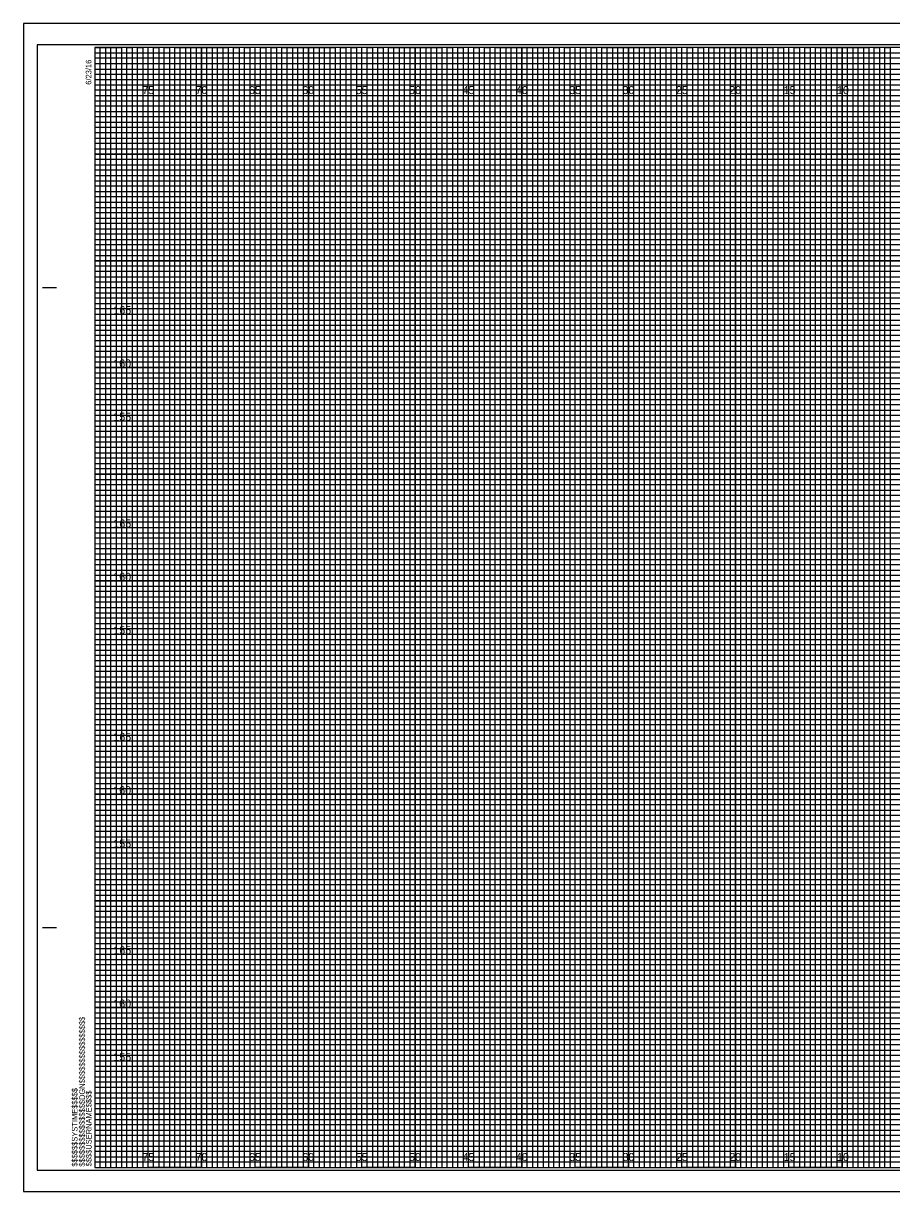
# Model space of a CAD drawing. Extents: x -7 to 162, y 328 to 437.
# Drawn here: x -6.7 to 74.6, y 327.7 to 437.2 of the extents above; entities that cross this region are included whole.
import ezdxf

# ---------------------------------------------------------------- set-up
doc = ezdxf.new("R2010")
doc.units = 0
for name, color, linetype in [('Exist Cross Section Cell', 7, 'Continuous'), ('Exist XS Center Line Elevation Label', 7, 'Continuous'), ('Exist XS Ground Line', 7, 'Continuous'), ('Prop CMT Conc Surface', 7, 'Continuous'), ('Prop CMT Concrete Structures', 7, 'Continuous'), ('Prop CMT Pvmt Course 1', 7, 'Continuous'), ('Prop CMT Pvmt Course 2', 7, 'Continuous'), ('Prop CMT Pvmt Course 3', 7, 'Continuous'), ('Prop CMT Slope Grass', 7, 'Continuous'), ('Prop CMT Subgrade Earthwork', 7, 'Continuous'), ('Scratch_Level_0', 7, 'Continuous')]:
    doc.layers.add(name, color=color, linetype=linetype)

msp = doc.modelspace()

# ---------------------------------------------------------------- linework, layer by layer
at = {"layer": 'Exist XS Center Line Elevation Label'}
for points in [[(0, 435), (2.5, 435), (2.5, 330), (7.5, 330), (7.5, 435), (12.5, 435), (12.5, 330), (17.5, 330), (17.5, 435), (22.5, 435), (22.5, 330), (27.5, 330), (27.5, 435), (32.5, 435), (32.5, 330), (37.5, 330), (37.5, 435), (42.5, 435), (42.5, 330), (47.5, 330), (47.5, 435), (52.5, 435), (52.5, 330), (57.5, 330), (57.5, 435), (62.5, 435), (62.5, 330), (67.5, 330), (67.5, 435), (72.5, 435), (72.5, 330), (77.5, 330)], [(0, 432.5), (137.5, 432.5)], [(0, 422.5), (160, 422.5), (160, 427.5), (0, 427.5)], [(0, 412.5), (160, 412.5), (160, 417.5), (0, 417.5)], [(0, 402.5), (160, 402.5), (160, 407.5), (0, 407.5)], [(0, 392.5), (160, 392.5), (160, 397.5), (0, 397.5)], [(0, 382.5), (160, 382.5), (160, 387.5), (0, 387.5)], [(0, 372.5), (160, 372.5), (160, 377.5), (0, 377.5)], [(0, 362.5), (160, 362.5), (160, 367.5), (0, 367.5)], [(0, 352.5), (160, 352.5), (160, 357.5), (0, 357.5)], [(0, 342.5), (160, 342.5), (160, 347.5), (0, 347.5)], [(0, 332.5), (160, 332.5), (160, 337.5), (0, 337.5)]]:
    msp.add_lwpolyline(points, dxfattribs=at)
at = {"layer": 'Exist XS Ground Line'}
for p, q in [((5, 435), (0, 435)), ((5, 330), (5, 435)), ((15, 435), (10, 435)), ((10, 435), (10, 330)), ((15, 330), (15, 435)), ((25, 435), (20, 435)), ((20, 435), (20, 330)), ((25, 330), (25, 435)), ((35, 435), (30, 435)), ((30, 435), (30, 330)), ((35, 330), (35, 435)), ((45, 435), (40, 435)), ((40, 435), (40, 330)), ((45, 330), (45, 435)), ((55, 435), (50, 435)), ((50, 435), (50, 330)), ((55, 330), (55, 435)), ((65, 435), (60, 435)), ((60, 435), (60, 330)), ((65, 330), (65, 435)), ((75, 435), (70, 435)), ((70, 435), (70, 330)), ((10, 330), (5, 330)), ((20, 330), (15, 330)), ((30, 330), (25, 330)), ((40, 330), (35, 330)), ((50, 330), (45, 330)), ((60, 330), (55, 330)), ((70, 330), (65, 330))]:
    msp.add_line(p, q, dxfattribs=at)
for points in [[(0, 430), (160, 430), (160, 425), (0, 425)], [(0, 420), (160, 420), (160, 415), (0, 415)], [(0, 410), (160, 410), (160, 405), (0, 405)], [(0, 400), (160, 400), (160, 395), (0, 395)], [(0, 390), (160, 390), (160, 385), (0, 385)], [(0, 380), (160, 380), (160, 375), (0, 375)], [(0, 370), (160, 370), (160, 365), (0, 365)], [(0, 360), (160, 360), (160, 355), (0, 355)], [(0, 350), (160, 350), (160, 345), (0, 345)], [(0, 340), (160, 340), (160, 335), (0, 335)]]:
    msp.add_lwpolyline(points, dxfattribs=at)
at = {"layer": 'Prop CMT Conc Surface'}
for p, q in [((5, 330), (5, 435)), ((10, 330), (10, 435)), ((15, 330), (15, 435)), ((20, 330), (20, 435)), ((25, 330), (25, 435)), ((30, 330), (30, 435)), ((35, 330), (35, 435)), ((40, 330), (40, 435)), ((45, 330), (45, 435)), ((50, 330), (50, 435)), ((55, 330), (55, 435)), ((60, 330), (60, 435)), ((65, 330), (65, 435)), ((70, 330), (70, 435)), ((0, 430), (160, 430)), ((0, 425), (160, 425)), ((0, 420), (160, 420)), ((0, 415), (160, 415)), ((0, 410), (160, 410)), ((0, 405), (160, 405)), ((0, 400), (160, 400)), ((0, 395), (160, 395)), ((0, 390), (160, 390)), ((0, 385), (160, 385)), ((0, 380), (160, 380)), ((0, 375), (160, 375)), ((0, 370), (160, 370)), ((0, 365), (160, 365)), ((0, 360), (160, 360)), ((0, 355), (160, 355)), ((0, 350), (160, 350)), ((0, 345), (160, 345)), ((0, 340), (160, 340)), ((0, 335), (160, 335))]:
    msp.add_line(p, q, dxfattribs=at)
at = {"layer": 'Prop CMT Pvmt Course 1'}
for points in [[(0, 330), (0.5, 330), (0.5, 435), (1, 435), (1, 330)], [(1, 330), (1.5, 330), (1.5, 435), (2, 435), (2, 330)], [(2.5, 330), (3, 330), (3, 435), (3.5, 435), (3.5, 330)], [(3.5, 330), (4, 330), (4, 435), (4.5, 435), (4.5, 330)], [(5, 330), (5.5, 330), (5.5, 435), (6, 435), (6, 330)], [(6, 330), (6.5, 330), (6.5, 435), (7, 435), (7, 330)], [(7.5, 330), (8, 330), (8, 435), (8.5, 435), (8.5, 330)], [(8.5, 330), (9, 330), (9, 435), (9.5, 435), (9.5, 330)], [(10, 330), (10.5, 330), (10.5, 435), (11, 435), (11, 330)], [(11, 330), (11.5, 330), (11.5, 435), (12, 435), (12, 330)], [(12.5, 330), (13, 330), (13, 435), (13.5, 435), (13.5, 330)], [(13.5, 330), (14, 330), (14, 435), (14.5, 435), (14.5, 330)], [(15, 330), (15.5, 330), (15.5, 435), (16, 435), (16, 330)], [(16, 330), (16.5, 330), (16.5, 435), (17, 435), (17, 330)], [(17.5, 330), (18, 330), (18, 435), (18.5, 435), (18.5, 330)], [(18.5, 330), (19, 330), (19, 435), (19.5, 435), (19.5, 330)], [(20, 330), (20.5, 330), (20.5, 435), (21, 435), (21, 330)], [(21, 330), (21.5, 330), (21.5, 435), (22, 435), (22, 330)], [(22.5, 330), (23, 330), (23, 435), (23.5, 435), (23.5, 330)], [(23.5, 330), (24, 330), (24, 435), (24.5, 435), (24.5, 330)], [(25, 330), (25.5, 330), (25.5, 435), (26, 435), (26, 330)], [(26, 330), (26.5, 330), (26.5, 435), (27, 435), (27, 330)], [(27.5, 330), (28, 330), (28, 435), (28.5, 435), (28.5, 330)], [(28.5, 330), (29, 330), (29, 435), (29.5, 435), (29.5, 330)], [(30, 330), (30.5, 330), (30.5, 435), (31, 435), (31, 330)], [(31, 330), (31.5, 330), (31.5, 435), (32, 435), (32, 330)], [(32.5, 330), (33, 330), (33, 435), (33.5, 435), (33.5, 330)], [(33.5, 330), (34, 330), (34, 435), (34.5, 435), (34.5, 330)], [(35, 330), (35.5, 330), (35.5, 435), (36, 435), (36, 330)], [(36, 330), (36.5, 330), (36.5, 435), (37, 435), (37, 330)], [(37.5, 330), (38, 330), (38, 435), (38.5, 435), (38.5, 330)], [(38.5, 330), (39, 330), (39, 435), (39.5, 435), (39.5, 330)], [(40, 330), (40.5, 330), (40.5, 435), (41, 435), (41, 330)], [(41, 330), (41.5, 330), (41.5, 435), (42, 435), (42, 330)], [(42.5, 330), (43, 330), (43, 435), (43.5, 435), (43.5, 330)], [(43.5, 330), (44, 330), (44, 435), (44.5, 435), (44.5, 330)], [(45, 330), (45.5, 330), (45.5, 435), (46, 435), (46, 330)], [(46, 330), (46.5, 330), (46.5, 435), (47, 435), (47, 330)], [(47.5, 330), (48, 330), (48, 435), (48.5, 435), (48.5, 330)], [(48.5, 330), (49, 330), (49, 435), (49.5, 435), (49.5, 330)], [(50, 330), (50.5, 330), (50.5, 435), (51, 435), (51, 330)], [(51, 330), (51.5, 330), (51.5, 435), (52, 435), (52, 330)], [(52.5, 330), (53, 330), (53, 435), (53.5, 435), (53.5, 330)], [(53.5, 330), (54, 330), (54, 435), (54.5, 435), (54.5, 330)], [(55, 330), (55.5, 330), (55.5, 435), (56, 435), (56, 330)], [(56, 330), (56.5, 330), (56.5, 435), (57, 435), (57, 330)], [(57.5, 330), (58, 330), (58, 435), (58.5, 435), (58.5, 330)], [(58.5, 330), (59, 330), (59, 435), (59.5, 435), (59.5, 330)], [(60, 330), (60.5, 330), (60.5, 435), (61, 435), (61, 330)], [(61, 330), (61.5, 330), (61.5, 435), (62, 435), (62, 330)], [(62.5, 330), (63, 330), (63, 435), (63.5, 435), (63.5, 330)], [(63.5, 330), (64, 330), (64, 435), (64.5, 435), (64.5, 330)], [(65, 330), (65.5, 330), (65.5, 435), (66, 435), (66, 330)], [(66, 330), (66.5, 330), (66.5, 435), (67, 435), (67, 330)], [(67.5, 330), (68, 330), (68, 435), (68.5, 435), (68.5, 330)], [(68.5, 330), (69, 330), (69, 435), (69.5, 435), (69.5, 330)], [(70, 330), (70.5, 330), (70.5, 435), (71, 435), (71, 330)], [(71, 330), (71.5, 330), (71.5, 435), (72, 435), (72, 330)], [(72.5, 330), (73, 330), (73, 435), (73.5, 435), (73.5, 330)], [(73.5, 330), (74, 330), (74, 435), (74.5, 435), (74.5, 330)]]:
    msp.add_lwpolyline(points, dxfattribs=at)
at = {"layer": 'Prop CMT Pvmt Course 2'}
msp.add_lwpolyline([(-6.7, 327.75), (161.65, 327.75), (161.65, 437.25), (-6.7, 437.25)], close=True, dxfattribs=at)
at = {"layer": 'Prop CMT Pvmt Course 3'}
msp.add_lwpolyline([(-5.4, 329.75), (161.2, 329.75), (161.2, 435.25), (-5.4, 435.25)], close=True, dxfattribs=at)
at = {"layer": 'Prop CMT Slope Grass'}
for p, q in [((161.65, 437.25), (-6.7, 437.25)), ((-6.7, 437.25), (-6.7, 327.75)), ((-6.7, 327.75), (161.65, 327.75))]:
    msp.add_line(p, q, dxfattribs=at)
at = {"layer": 'Prop CMT Subgrade Earthwork'}
for p, q in [((-4.9, 412.5), (-3.65, 412.5)), ((-4.85, 412.5), (-3.6, 412.5)), ((-4.9, 352.5), (-3.65, 352.5)), ((-4.85, 352.5), (-3.6, 352.5)), ((0, 330), (0, 330)), ((0, 330), (0, 330)), ((0, 330), (0, 330)), ((0, 330), (0, 330)), ((0, 330), (0, 330)), ((0, 330), (0, 330)), ((0, 330), (0, 330))]:
    msp.add_line(p, q, dxfattribs=at)
msp.add_lwpolyline([(160, 435), (0, 435), (0, 330), (160, 330)], close=True, dxfattribs=at)
at = {"layer": 'Scratch_Level_0'}
for p, q in [((0, 434.5), (130, 434.5)), ((130, 433.99), (0, 433.99)), ((0, 433.99), (0, 433.5)), ((0, 433.5), (130, 433.5)), ((130, 432.94), (0, 432.94)), ((0, 432.94), (0, 432)), ((0, 432), (160, 432))]:
    msp.add_line(p, q, dxfattribs=at)
for points in [[(0, 431.5), (135, 431.5), (160, 431.5), (160, 431), (0, 431)], [(0, 430.5), (160, 430.5), (160, 429.5), (0, 429.5)], [(0, 429), (160, 429), (160, 428.5), (0, 428.49)], [(0, 428), (160, 428), (160, 427), (0, 427)], [(0, 426.5), (160, 426.5), (160, 426), (0, 426)], [(0, 425.5), (160, 425.5), (160, 424.5), (0, 424.5)], [(0, 424), (160, 424), (160, 423.5), (0, 423.5)], [(0, 423), (160, 423), (160, 422), (0, 422)], [(0, 421.5), (160, 421.5), (160, 421), (0, 421)], [(0, 420.5), (160, 420.5), (160, 419.5), (0, 419.5)], [(0, 419), (160, 419), (160, 418.5), (0, 418.5)], [(0, 418), (160, 418), (160, 416.98), (160, 416.5), (160, 416), (0, 416)], [(0, 417), (160, 417), (160, 416.5), (0, 416.5)], [(0, 415.5), (160, 415.5), (160, 414.5), (0, 414.51)], [(0, 414.51), (160, 414.5), (160, 414), (0, 414)], [(0, 413.5), (160, 413.5), (160, 413), (0, 413)], [(0, 412), (160, 412), (160, 411.5), (0, 411.5)], [(0, 411), (160, 411), (160, 410.5), (0, 410.5)], [(-0.04, 409.44), (160, 409.44), (160, 408.94), (-0.04, 408.94)], [(0, 408.5), (160, 408.5), (160, 408), (0, 408)], [(0, 407), (160, 407), (160, 406.5), (0, 406.5)], [(0, 406), (160, 406), (160, 405.5), (0, 405.5)], [(0, 404.5), (160, 404.5), (160, 404), (0, 404)], [(0, 403.5), (160, 403.5), (160, 403), (0, 403)], [(0, 402), (160, 402), (160, 401.5), (0, 401.5)], [(0, 401), (160, 401), (160, 400.5), (0, 400.5)], [(0, 399.5), (160, 399.5), (160, 398.99), (0, 399)], [(0, 398.5), (160, 398.5), (160, 398), (0, 398)], [(0, 397), (160, 397), (160, 396.5), (0, 396.5)], [(0, 396), (160, 396), (160, 395.5), (0, 395.5)], [(0, 394.5), (160, 394.5), (160, 394), (0, 394)], [(0, 393.5), (160, 393.5), (160, 393), (0, 393)], [(0, 392), (160, 392), (160, 391.5), (0, 391.5)], [(0, 391), (160, 391), (160, 390.5), (0, 390.5)], [(0, 389.5), (160, 389.5), (160, 389), (0, 389)], [(0, 388.5), (160.03, 388.45), (160, 388), (0, 388)], [(0, 387), (160, 387), (160, 386.5), (0, 386.5)], [(0, 386), (160, 386), (160, 385.5), (0, 385.5)], [(0, 384.5), (160, 384.5), (160, 384), (0, 384)], [(0, 383.5), (160, 383.5), (160, 383), (0, 383)], [(0, 382), (160, 382), (160, 381.5), (0, 381.5)], [(0, 381), (160, 381), (160, 380.5), (0, 380.5)], [(0, 379.5), (160, 379.5), (160, 379), (0, 379)], [(0, 378.5), (160, 378.5), (160, 378), (0, 378)], [(0, 377), (160, 377), (160, 376.5), (0, 376.5)], [(0, 376), (160, 376), (160, 375.5), (0, 375.5)], [(0, 374.5), (160, 374.5), (160, 374), (0, 374)], [(0, 373.5), (160, 373.5), (160, 373), (0, 373)], [(0, 372), (160, 372), (160, 371.5), (0, 371.5)], [(0, 371), (160, 371), (160, 370.5), (0, 370.5)], [(0, 369.5), (160, 369.5), (160, 368.99), (0, 369)], [(0, 368.5), (160, 368.5), (160, 368), (0, 368)], [(0, 367), (160, 367), (160, 366.5), (0, 366.5)], [(0, 366), (160, 366), (160, 365.5), (0, 365.5)], [(0, 364.5), (160, 364.5), (160, 364), (0, 364)], [(0, 363.5), (160, 363.5), (160, 363), (0, 363)], [(0, 362), (160, 362), (160, 361.5), (0, 361.5)], [(0, 361), (160, 361), (160, 360.5), (0, 360.5)], [(0, 359.5), (160, 359.5), (160, 359), (0, 359)], [(0, 358.5), (160.03, 358.45), (160, 358), (0, 358)], [(0, 357), (160, 357), (160, 356.5), (0, 356.5)], [(0, 356), (160, 356), (160, 355.5), (0, 355.5)], [(0, 354.5), (160, 354.5), (160, 354), (0, 354)], [(0, 353.5), (160, 353.5), (160, 353), (0, 353)], [(0, 352), (160, 352), (160, 351.5), (0, 351.5)], [(0, 351), (160, 351), (160, 350.5), (0, 350.5)], [(0, 349.5), (160, 349.5), (160, 349), (0, 349)], [(0, 348.5), (160, 348.5), (160, 348), (0, 348)], [(0, 347), (160, 347), (160, 346.5), (0, 346.5)], [(0, 346), (160, 346), (160, 345.5), (0, 345.5)], [(0, 344.5), (160, 344.5), (160, 344), (0, 344)], [(0, 343.5), (160, 343.5), (160, 343), (0, 343)], [(0, 342), (160, 342), (160, 341.5), (0, 341.5)], [(0, 341), (160, 341), (160, 340.5), (0, 340.5)], [(0, 339.5), (160, 339.5), (160, 339), (0, 339)], [(0, 338.5), (160, 338.5), (160, 338), (0, 338)], [(0, 337), (160, 337), (160, 336.5), (0, 336.5)], [(0, 336), (160, 336), (160, 335.5), (0, 335.5)], [(0, 334.5), (160, 334.5), (160, 334), (0, 334)], [(0, 333.5), (160, 333.5), (160, 333), (0, 333)], [(0, 332), (160, 332), (160, 331.5), (0, 331.5)], [(0, 331), (160, 331), (160, 330.5), (0, 330.5)]]:
    msp.add_lwpolyline(points, dxfattribs=at)

# ---------------------------------------------------------------- texts
at = {"layer": 'Exist Cross Section Cell'}
for s, p in [('75', (4.44, 430.62)), ('70', (9.43, 430.62)), ('65', (14.44, 430.62)), ('60', (19.43, 430.62)), ('55', (24.44, 430.62)), ('50', (29.43, 430.62)), ('45', (34.44, 430.62)), ('40', (39.43, 430.62)), ('35', (44.44, 430.62)), ('30', (49.43, 430.62)), ('25', (54.44, 430.62)), ('20', (59.43, 430.62)), ('15', (64.53, 430.62)), ('10', (69.52, 430.62)), ('75', (4.44, 330.62)), ('70', (9.43, 330.62)), ('65', (14.44, 330.62)), ('60', (19.43, 330.62)), ('55', (24.44, 330.62)), ('50', (29.43, 330.62)), ('45', (34.44, 330.62)), ('40', (39.43, 330.62)), ('35', (44.44, 330.62)), ('30', (49.43, 330.62)), ('25', (54.44, 330.62)), ('20', (59.43, 330.62)), ('15', (64.53, 330.62)), ('10', (69.52, 330.62))]:
    msp.add_text(s, height=0.75, dxfattribs=at).set_placement(p)
at = {"layer": 'Prop CMT Concrete Structures'}
for s, p in [('165', (1.73, 410)), ('160', (1.72, 405)), ('155', (1.73, 400)), ('165', (1.73, 390)), ('160', (1.72, 385)), ('155', (1.73, 380)), ('165', (1.73, 370)), ('160', (1.72, 365)), ('155', (1.73, 360)), ('165', (1.73, 350)), ('160', (1.72, 345)), ('155', (1.73, 340))]:
    msp.add_text(s, height=0.75, dxfattribs=at).set_placement(p)
at = {"layer": 'Prop CMT Subgrade Earthwork'}
for s, p in [('6/23/16', (-0.33, 431.5)), ('$$$$$$$$$$$$$$$$DGN$$$$$$$$$$$$$$$$', (-0.94, 330.09)), ('$$$$$$SYSTIME$$$$$', (-1.63, 330.09)), ('$$$$USERNAME$$$$', (-0.31, 330.12))]:
    msp.add_text(s, height=0.525, rotation=90, dxfattribs=at).set_placement(p)

doc.saveas('drawing.dxf')
